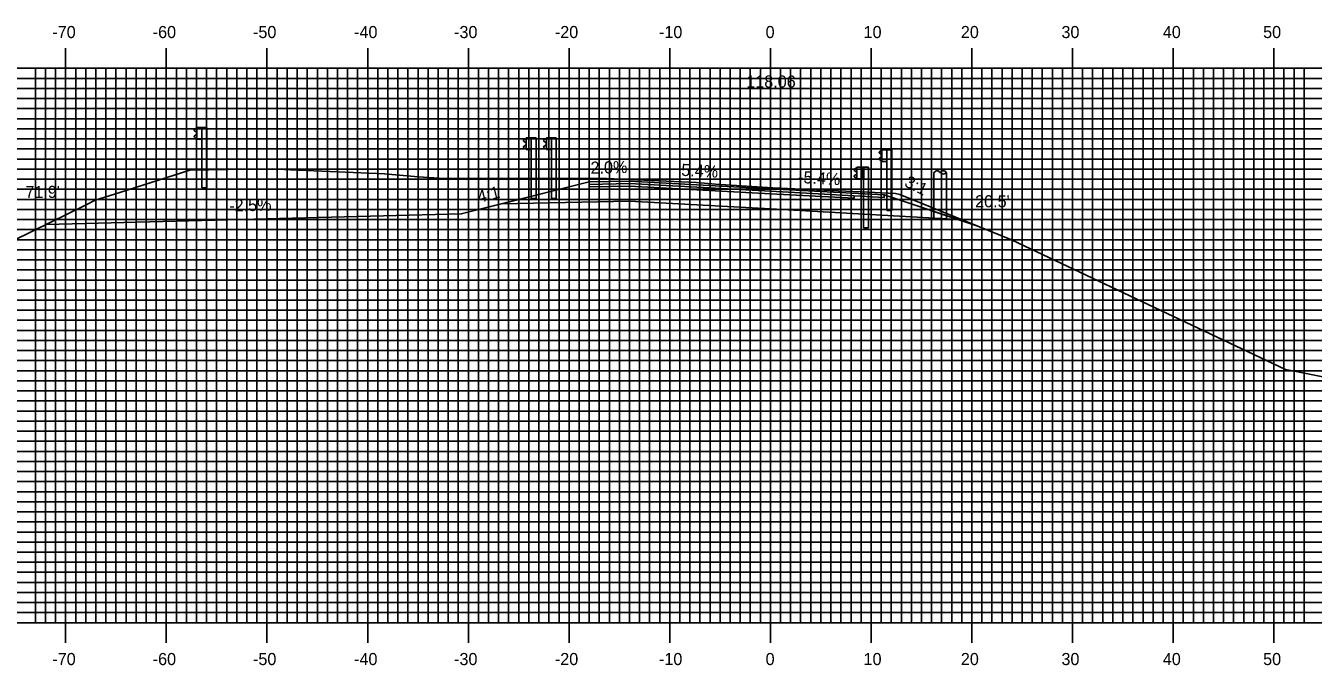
# Model space of a CAD drawing. Extents: x 1684012 to 1684355, y 461260 to 461480.
# Drawn here: x 1684103.7 to 1684231.6, y 461348.9 to 461412.3 of the extents above; entities that cross this region are included whole.
import ezdxf

# ---------------------------------------------------------------- set-up
doc = ezdxf.new("R2010")
doc.units = 0
for name, color, linetype in [('ANNOTATION', 7, 'Continuous'), ('D_Guardrail_Beam_Rt', 7, 'Continuous'), ('D_Roadway_Centerline', 7, 'Continuous'), ('D_Roadway_Centerline_Text', 7, 'Continuous'), ('D_Roadway_Edge_Shoulder', 7, 'Continuous'), ('D_Roadway_Edge_TW', 7, 'Continuous'), ('D_Roadway_Pavement', 7, 'Continuous'), ('D_Roadway_SlopeLines', 7, 'Continuous'), ('D_Roadway_SubGrade', 7, 'Continuous'), ('D_Text_Standard', 7, 'Continuous'), ('H_V ANNOTATION', 7, 'Continuous'), ('M_Guardrail', 7, 'Continuous'), ('M_Roadway_Centerline', 7, 'Continuous'), ('M_Utilities_Pole_StreetLight', 7, 'Continuous'), ('MAJOR', 7, 'Continuous'), ('MINOR', 7, 'Continuous'), ('S_Roadway_Centerline', 7, 'Continuous')]:
    doc.layers.add(name, color=color, linetype=linetype)

msp = doc.modelspace()

# ---------------------------------------------------------------- linework, layer by layer
at = {"layer": 'D_Guardrail_Beam_Rt'}
for p, q in [((1684186.17, 461398.16), (1684186.03, 461398.06)), ((1684186.03, 461397.92), (1684186.22, 461397.78)), ((1684186.22, 461397.58), (1684186.03, 461397.45)), ((1684186.03, 461397.3), (1684186.17, 461397.2)), ((1684186.26, 461398.18), (1684186.19, 461398.17)), ((1684186.19, 461397.2), (1684186.26, 461397.18)), ((1684186.26, 461398.26), (1684186.95, 461398.26)), ((1684186.26, 461397.1), (1684186.26, 461398.26)), ((1684186.26, 461397.72), (1684186.26, 461397.65)), ((1684186.78, 461398.26), (1684186.78, 461397.1)), ((1684186.89, 461398.26), (1684186.89, 461397.1)), ((1684186.95, 461398.26), (1684187.42, 461398.26)), ((1684186.95, 461398.26), (1684186.95, 461397.1)), ((1684187.42, 461398.26), (1684187.42, 461392.26)), ((1684186.95, 461397.1), (1684186.26, 461397.1)), ((1684186.93, 461392.26), (1684186.93, 461397.1)), ((1684186.93, 461392.26), (1684187.42, 461392.26))]:
    msp.add_line(p, q, dxfattribs=at)
for centre, major_axis, start_param, end_param in [((1684186.08, 461397.99), (-0.0877, 0), 5.323254, 7.243116), ((1684186.08, 461397.37), (-0.0877, 0), 5.323254, 7.243116), ((1684186.19, 461398.13), (-0.0417, 0), 4.907132, 5.323254), ((1684186.19, 461397.24), (-0.0417, 0), 0.959931, 1.376053), ((1684186.18, 461397.72), (0.0789, 0), 0, 0.959931), ((1684186.18, 461397.65), (0.0789, 0), 5.323254, 6.283185)]:
    msp.add_ellipse(centre, major_axis=major_axis, ratio=0.995501, start_param=start_param, end_param=end_param, dxfattribs=at)
at = {"layer": 'D_Roadway_Centerline'}
msp.add_lwpolyline([(1684105.77, 461392.59), (1684146.99, 461393.63), (1684150.99, 461394.63), (1684159.69, 461396.8), (1684163.69, 461396.88), (1684177.69, 461396.13), (1684187.69, 461395.59), (1684188.99, 461395.52), (1684198.19, 461392.45)], dxfattribs=at)
at = {"layer": 'D_Roadway_Edge_Shoulder'}
for points in [[(1684163.69, 461396.88), (1684159.69, 461396.8), (1684159.69, 461396.55), (1684163.69, 461396.63)], [(1684177.69, 461396.13), (1684187.69, 461395.59), (1684187.69, 461395.59), (1684188.99, 461395.52), (1684188.99, 461395.27), (1684177.69, 461395.88)], [(1684177.69, 461395.88), (1684185.99, 461395.43), (1684185.99, 461395.43), (1684185.99, 461395.43), (1684185.99, 461395.18), (1684177.69, 461395.63)]]:
    msp.add_lwpolyline(points, close=True, dxfattribs=at)
at = {"layer": 'D_Roadway_Edge_TW'}
msp.add_lwpolyline([(1684163.69, 461396.88), (1684177.69, 461396.13), (1684177.69, 461395.88), (1684163.69, 461396.63)], close=True, dxfattribs=at)
at = {"layer": 'D_Roadway_Pavement'}
for points in [[(1684163.69, 461396.63), (1684159.69, 461396.55), (1684159.69, 461396.3), (1684163.69, 461396.38)], [(1684163.69, 461396.63), (1684177.69, 461395.88), (1684177.69, 461395.63), (1684163.69, 461396.38)]]:
    msp.add_lwpolyline(points, close=True, dxfattribs=at)
msp.add_lwpolyline([(1684177.69, 461395.88), (1684177.69, 461395.63)], dxfattribs=at)
msp.add_lwpolyline([(1684177.69, 461395.88), (1684177.69, 461395.63)], dxfattribs=at)
msp.add_lwpolyline([(1684177.69, 461395.88), (1684177.69, 461395.63)], dxfattribs=at)
at = {"layer": 'D_Roadway_SlopeLines'}
for points in [[(1684159.69, 461396.8), (1684146.99, 461393.63)], [(1684146.99, 461393.63), (1684105.77, 461392.59)]]:
    msp.add_lwpolyline(points, dxfattribs=at)
at = {"layer": 'D_Roadway_SubGrade'}
for points in [[(1684163.69, 461396.38), (1684159.69, 461396.3), (1684159.69, 461396.55), (1684159.69, 461396.8), (1684150.99, 461394.63), (1684163.69, 461394.88)], [(1684163.69, 461396.38), (1684177.69, 461395.63), (1684177.69, 461394.13), (1684163.69, 461394.88)], [(1684177.69, 461395.63), (1684177.69, 461395.88), (1684188.99, 461395.27), (1684188.99, 461395.52), (1684196.33, 461393.07), (1684177.69, 461394.13)]]:
    msp.add_lwpolyline(points, close=True, dxfattribs=at)
at = {"layer": 'M_Guardrail'}
for p, q in [((1684120.63, 461402.1), (1684120.49, 461402)), ((1684120.49, 461401.86), (1684120.68, 461401.72)), ((1684120.68, 461401.5), (1684120.49, 461401.37)), ((1684120.49, 461401.22), (1684120.63, 461401.12)), ((1684120.73, 461402.12), (1684120.65, 461402.11)), ((1684120.65, 461401.12), (1684120.73, 461401.1)), ((1684120.72, 461401.66), (1684120.72, 461401.57)), ((1684120.73, 461402.2), (1684121.22, 461402.2)), ((1684120.73, 461401.03), (1684120.73, 461402.2)), ((1684121.22, 461401.03), (1684120.73, 461401.03)), ((1684121.22, 461402.2), (1684121.71, 461402.2)), ((1684121.22, 461402.2), (1684121.22, 461401.03)), ((1684121.22, 461396.2), (1684121.22, 461401.03)), ((1684121.71, 461402.2), (1684121.71, 461396.2)), ((1684153.34, 461401.07), (1684153.2, 461400.97)), ((1684153.44, 461401.09), (1684153.36, 461401.08)), ((1684153.44, 461401.16), (1684153.93, 461401.16)), ((1684153.44, 461400), (1684153.44, 461401.16)), ((1684153.93, 461401.16), (1684154.42, 461401.16)), ((1684153.93, 461401.16), (1684153.93, 461400)), ((1684154.42, 461401.16), (1684154.42, 461395.16)), ((1684155.34, 461401.07), (1684155.2, 461400.97)), ((1684155.44, 461401.09), (1684155.36, 461401.08)), ((1684155.44, 461401.16), (1684155.93, 461401.16)), ((1684155.44, 461400), (1684155.44, 461401.16)), ((1684155.93, 461401.16), (1684156.42, 461401.16)), ((1684155.93, 461401.16), (1684155.93, 461400)), ((1684156.42, 461401.16), (1684156.42, 461395.16)), ((1684153.2, 461400.83), (1684153.4, 461400.69)), ((1684153.4, 461400.47), (1684153.2, 461400.33)), ((1684153.2, 461400.19), (1684153.34, 461400.09)), ((1684153.36, 461400.08), (1684153.44, 461400.07)), ((1684153.43, 461400.62), (1684153.43, 461400.53)), ((1684153.93, 461400), (1684153.44, 461400)), ((1684153.93, 461395.16), (1684153.93, 461400)), ((1684155.2, 461400.83), (1684155.4, 461400.69)), ((1684155.4, 461400.47), (1684155.2, 461400.33)), ((1684155.2, 461400.19), (1684155.34, 461400.09)), ((1684155.36, 461400.08), (1684155.44, 461400.07)), ((1684155.43, 461400.62), (1684155.43, 461400.53)), ((1684155.93, 461400), (1684155.44, 461400)), ((1684155.93, 461395.16), (1684155.93, 461400)), ((1684188.66, 461399.89), (1684188.52, 461399.79)), ((1684188.76, 461399.91), (1684188.68, 461399.9)), ((1684188.76, 461399.98), (1684189.25, 461399.98)), ((1684188.76, 461398.82), (1684188.76, 461399.98)), ((1684189.25, 461399.98), (1684189.74, 461399.98)), ((1684189.25, 461399.98), (1684189.25, 461398.82)), ((1684189.74, 461399.98), (1684189.74, 461393.98)), ((1684188.52, 461399.65), (1684188.72, 461399.51)), ((1684188.72, 461399.29), (1684188.52, 461399.15)), ((1684188.52, 461399.01), (1684188.66, 461398.91)), ((1684188.68, 461398.9), (1684188.76, 461398.89)), ((1684188.75, 461399.45), (1684188.75, 461399.35)), ((1684189.25, 461398.82), (1684188.76, 461398.82)), ((1684189.25, 461393.98), (1684189.25, 461398.82)), ((1684121.22, 461396.2), (1684121.71, 461396.2)), ((1684153.93, 461395.16), (1684154.42, 461395.16)), ((1684155.93, 461395.16), (1684156.42, 461395.16)), ((1684189.25, 461393.98), (1684189.74, 461393.98))]:
    msp.add_line(p, q, dxfattribs=at)
for centre, major_axis, start_param, end_param in [((1684120.54, 461401.93), (-0.0877, 0), 5.323254, 7.243116), ((1684120.54, 461401.3), (-0.0877, 0), 5.323254, 7.243116), ((1684120.65, 461402.07), (-0.0417, 0), 4.886922, 5.323254), ((1684120.65, 461401.16), (-0.0417, 0), 0.959931, 1.396263), ((1684120.64, 461401.66), (0.0789, 0), 0, 0.959931), ((1684120.64, 461401.57), (0.0789, 0), 5.323254, 6.283185), ((1684153.37, 461401.03), (-0.0417, 0), 4.886922, 5.323254), ((1684155.37, 461401.03), (-0.0417, 0), 4.886922, 5.323254), ((1684153.25, 461400.9), (-0.0877, 0), 5.323254, 7.243116), ((1684153.25, 461400.26), (-0.0877, 0), 5.323254, 7.243116), ((1684153.37, 461400.12), (-0.0417, 0), 0.959931, 1.396263), ((1684153.35, 461400.62), (0.0789, 0), 0, 0.959931), ((1684153.35, 461400.53), (0.0789, 0), 5.323254, 6.283185), ((1684155.25, 461400.9), (-0.0877, 0), 5.323254, 7.243116), ((1684155.25, 461400.26), (-0.0877, 0), 5.323254, 7.243116), ((1684155.37, 461400.12), (-0.0417, 0), 0.959931, 1.396263), ((1684155.35, 461400.62), (0.0789, 0), 0, 0.959931), ((1684155.35, 461400.53), (0.0789, 0), 5.323254, 6.283185), ((1684188.57, 461399.72), (-0.0877, 0), 5.323254, 7.243116), ((1684188.69, 461399.86), (-0.0417, 0), 4.886922, 5.323254), ((1684188.57, 461399.08), (-0.0877, 0), 5.323254, 7.243116), ((1684188.69, 461398.95), (-0.0417, 0), 0.959931, 1.396263), ((1684188.67, 461399.45), (0.0789, 0), 0, 0.959931), ((1684188.67, 461399.35), (0.0789, 0), 5.323254, 6.283185)]:
    msp.add_ellipse(centre, major_axis=major_axis, ratio=0.995501, start_param=start_param, end_param=end_param, dxfattribs=at)
at = {"layer": 'M_Utilities_Pole_StreetLight'}
for p, q in [((1684193.93, 461397.74), (1684194.09, 461397.85)), ((1684193.93, 461393.12), (1684193.93, 461397.74)), ((1684194.4, 461397.85), (1684194.56, 461397.74)), ((1684194.72, 461397.85), (1684194.56, 461397.74)), ((1684194.56, 461397.74), (1684194.72, 461397.63)), ((1684195.18, 461397.74), (1684195.03, 461397.85)), ((1684195.03, 461397.63), (1684195.18, 461397.74)), ((1684195.18, 461393.12), (1684195.18, 461397.74))]:
    msp.add_line(p, q, dxfattribs=at)
for centre, start, end in [((1684194.25, 461397.63), 90, 125.2644), ((1684194.25, 461397.63), 54.7356, 90), ((1684194.87, 461397.63), 90, 125.2644), ((1684194.87, 461397.85), 234.7356, 270), ((1684194.87, 461397.63), 54.7356, 90), ((1684194.87, 461397.85), 270, 305.2644)]:
    msp.add_arc(centre, 0.271, start, end, dxfattribs=at)
at = {"layer": 'MAJOR'}
for p, q in [((1684107.69, 461410.08), (1684107.69, 461408.07)), ((1684117.69, 461410.08), (1684117.69, 461408.07)), ((1684127.69, 461410.08), (1684127.69, 461408.07)), ((1684137.69, 461410.08), (1684137.69, 461408.07)), ((1684147.69, 461410.08), (1684147.69, 461408.07)), ((1684157.69, 461410.08), (1684157.69, 461408.07)), ((1684167.69, 461410.08), (1684167.69, 461408.07)), ((1684177.69, 461410.08), (1684177.69, 461408.07)), ((1684187.69, 461410.08), (1684187.69, 461408.07)), ((1684197.69, 461410.08), (1684197.69, 461408.07)), ((1684207.69, 461410.08), (1684207.69, 461408.07)), ((1684217.69, 461410.08), (1684217.69, 461408.07)), ((1684227.69, 461410.08), (1684227.69, 461408.07)), ((1684037.69, 461408.07), (1684317.69, 461408.07)), ((1684037.69, 461408.07), (1684317.69, 461408.07)), ((1684107.69, 461353.07), (1684107.69, 461408.07)), ((1684117.69, 461353.07), (1684117.69, 461408.07)), ((1684127.69, 461353.07), (1684127.69, 461408.07)), ((1684137.69, 461353.07), (1684137.69, 461408.07)), ((1684147.69, 461353.07), (1684147.69, 461408.07)), ((1684157.69, 461353.07), (1684157.69, 461408.07)), ((1684167.69, 461353.07), (1684167.69, 461408.07)), ((1684177.69, 461353.07), (1684177.69, 461408.07)), ((1684187.69, 461353.07), (1684187.69, 461408.07)), ((1684197.69, 461353.07), (1684197.69, 461408.07)), ((1684207.69, 461353.07), (1684207.69, 461408.07)), ((1684217.69, 461353.07), (1684217.69, 461408.07)), ((1684227.69, 461353.07), (1684227.69, 461408.07)), ((1684037.69, 461403.07), (1684317.69, 461403.07)), ((1684037.69, 461398.07), (1684317.69, 461398.07)), ((1684037.69, 461393.07), (1684317.69, 461393.07)), ((1684037.69, 461388.07), (1684317.69, 461388.07)), ((1684037.69, 461383.07), (1684317.69, 461383.07)), ((1684037.69, 461378.07), (1684317.69, 461378.07)), ((1684037.69, 461373.07), (1684317.69, 461373.07)), ((1684037.69, 461368.07), (1684317.69, 461368.07)), ((1684037.69, 461363.07), (1684317.69, 461363.07)), ((1684037.69, 461358.07), (1684317.69, 461358.07)), ((1684037.69, 461353.07), (1684317.69, 461353.07)), ((1684037.69, 461353.07), (1684317.69, 461353.07)), ((1684107.69, 461351.07), (1684107.69, 461353.07)), ((1684117.69, 461351.07), (1684117.69, 461353.07)), ((1684127.69, 461351.07), (1684127.69, 461353.07)), ((1684137.69, 461351.07), (1684137.69, 461353.07)), ((1684147.69, 461351.07), (1684147.69, 461353.07)), ((1684157.69, 461351.07), (1684157.69, 461353.07)), ((1684167.69, 461351.07), (1684167.69, 461353.07)), ((1684177.69, 461351.07), (1684177.69, 461353.07)), ((1684187.69, 461351.07), (1684187.69, 461353.07)), ((1684197.69, 461351.07), (1684197.69, 461353.07)), ((1684207.69, 461351.07), (1684207.69, 461353.07)), ((1684217.69, 461351.07), (1684217.69, 461353.07)), ((1684227.69, 461351.07), (1684227.69, 461353.07))]:
    msp.add_line(p, q, dxfattribs=at)
at = {"layer": 'MINOR'}
for p, q in [((1684104.69, 461353.07), (1684104.69, 461408.07)), ((1684105.69, 461353.07), (1684105.69, 461408.07)), ((1684106.69, 461353.07), (1684106.69, 461408.07)), ((1684108.69, 461353.07), (1684108.69, 461408.07)), ((1684109.69, 461353.07), (1684109.69, 461408.07)), ((1684110.69, 461353.07), (1684110.69, 461408.07)), ((1684111.69, 461353.07), (1684111.69, 461408.07)), ((1684112.69, 461353.07), (1684112.69, 461408.07)), ((1684113.69, 461353.07), (1684113.69, 461408.07)), ((1684114.69, 461353.07), (1684114.69, 461408.07)), ((1684115.69, 461353.07), (1684115.69, 461408.07)), ((1684116.69, 461353.07), (1684116.69, 461408.07)), ((1684118.69, 461353.07), (1684118.69, 461408.07)), ((1684119.69, 461353.07), (1684119.69, 461408.07)), ((1684120.69, 461353.07), (1684120.69, 461408.07)), ((1684121.69, 461353.07), (1684121.69, 461408.07)), ((1684122.69, 461353.07), (1684122.69, 461408.07)), ((1684123.69, 461353.07), (1684123.69, 461408.07)), ((1684124.69, 461353.07), (1684124.69, 461408.07)), ((1684125.69, 461353.07), (1684125.69, 461408.07)), ((1684126.69, 461353.07), (1684126.69, 461408.07)), ((1684128.69, 461353.07), (1684128.69, 461408.07)), ((1684129.69, 461353.07), (1684129.69, 461408.07)), ((1684130.69, 461353.07), (1684130.69, 461408.07)), ((1684131.69, 461353.07), (1684131.69, 461408.07)), ((1684132.69, 461353.07), (1684132.69, 461408.07)), ((1684133.69, 461353.07), (1684133.69, 461408.07)), ((1684134.69, 461353.07), (1684134.69, 461408.07)), ((1684135.69, 461353.07), (1684135.69, 461408.07)), ((1684136.69, 461353.07), (1684136.69, 461408.07)), ((1684138.69, 461353.07), (1684138.69, 461408.07)), ((1684139.69, 461353.07), (1684139.69, 461408.07)), ((1684140.69, 461353.07), (1684140.69, 461408.07)), ((1684141.69, 461353.07), (1684141.69, 461408.07)), ((1684142.69, 461353.07), (1684142.69, 461408.07)), ((1684143.69, 461353.07), (1684143.69, 461408.07)), ((1684144.69, 461353.07), (1684144.69, 461408.07)), ((1684145.69, 461353.07), (1684145.69, 461408.07)), ((1684146.69, 461353.07), (1684146.69, 461408.07)), ((1684148.69, 461353.07), (1684148.69, 461408.07)), ((1684149.69, 461353.07), (1684149.69, 461408.07)), ((1684150.69, 461353.07), (1684150.69, 461408.07)), ((1684151.69, 461353.07), (1684151.69, 461408.07)), ((1684152.69, 461353.07), (1684152.69, 461408.07)), ((1684153.69, 461353.07), (1684153.69, 461408.07)), ((1684154.69, 461353.07), (1684154.69, 461408.07)), ((1684155.69, 461353.07), (1684155.69, 461408.07)), ((1684156.69, 461353.07), (1684156.69, 461408.07)), ((1684158.69, 461353.07), (1684158.69, 461408.07)), ((1684159.69, 461353.07), (1684159.69, 461408.07)), ((1684160.69, 461353.07), (1684160.69, 461408.07)), ((1684161.69, 461353.07), (1684161.69, 461408.07)), ((1684162.69, 461353.07), (1684162.69, 461408.07)), ((1684163.69, 461353.07), (1684163.69, 461408.07)), ((1684164.69, 461353.07), (1684164.69, 461408.07)), ((1684165.69, 461353.07), (1684165.69, 461408.07)), ((1684166.69, 461353.07), (1684166.69, 461408.07)), ((1684168.69, 461353.07), (1684168.69, 461408.07)), ((1684169.69, 461353.07), (1684169.69, 461408.07)), ((1684170.69, 461353.07), (1684170.69, 461408.07)), ((1684171.69, 461353.07), (1684171.69, 461408.07)), ((1684172.69, 461353.07), (1684172.69, 461408.07)), ((1684173.69, 461353.07), (1684173.69, 461408.07)), ((1684174.69, 461353.07), (1684174.69, 461408.07)), ((1684175.69, 461353.07), (1684175.69, 461408.07)), ((1684176.69, 461353.07), (1684176.69, 461408.07)), ((1684178.69, 461353.07), (1684178.69, 461408.07)), ((1684179.69, 461353.07), (1684179.69, 461408.07)), ((1684180.69, 461353.07), (1684180.69, 461408.07)), ((1684181.69, 461353.07), (1684181.69, 461408.07)), ((1684182.69, 461353.07), (1684182.69, 461408.07)), ((1684183.69, 461353.07), (1684183.69, 461408.07)), ((1684184.69, 461353.07), (1684184.69, 461408.07)), ((1684185.69, 461353.07), (1684185.69, 461408.07)), ((1684186.69, 461353.07), (1684186.69, 461408.07)), ((1684188.69, 461353.07), (1684188.69, 461408.07)), ((1684189.69, 461353.07), (1684189.69, 461408.07)), ((1684190.69, 461353.07), (1684190.69, 461408.07)), ((1684191.69, 461353.07), (1684191.69, 461408.07)), ((1684192.69, 461353.07), (1684192.69, 461408.07)), ((1684193.69, 461353.07), (1684193.69, 461408.07)), ((1684194.69, 461353.07), (1684194.69, 461408.07)), ((1684195.69, 461353.07), (1684195.69, 461408.07)), ((1684196.69, 461353.07), (1684196.69, 461408.07)), ((1684198.69, 461353.07), (1684198.69, 461408.07)), ((1684199.69, 461353.07), (1684199.69, 461408.07)), ((1684200.69, 461353.07), (1684200.69, 461408.07)), ((1684201.69, 461353.07), (1684201.69, 461408.07)), ((1684202.69, 461353.07), (1684202.69, 461408.07)), ((1684203.69, 461353.07), (1684203.69, 461408.07)), ((1684204.69, 461353.07), (1684204.69, 461408.07)), ((1684205.69, 461353.07), (1684205.69, 461408.07)), ((1684206.69, 461353.07), (1684206.69, 461408.07)), ((1684208.69, 461353.07), (1684208.69, 461408.07)), ((1684209.69, 461353.07), (1684209.69, 461408.07)), ((1684210.69, 461353.07), (1684210.69, 461408.07)), ((1684211.69, 461353.07), (1684211.69, 461408.07)), ((1684212.69, 461353.07), (1684212.69, 461408.07)), ((1684213.69, 461353.07), (1684213.69, 461408.07)), ((1684214.69, 461353.07), (1684214.69, 461408.07)), ((1684215.69, 461353.07), (1684215.69, 461408.07)), ((1684216.69, 461353.07), (1684216.69, 461408.07)), ((1684218.69, 461353.07), (1684218.69, 461408.07)), ((1684219.69, 461353.07), (1684219.69, 461408.07)), ((1684220.69, 461353.07), (1684220.69, 461408.07)), ((1684221.69, 461353.07), (1684221.69, 461408.07)), ((1684222.69, 461353.07), (1684222.69, 461408.07)), ((1684223.69, 461353.07), (1684223.69, 461408.07)), ((1684224.69, 461353.07), (1684224.69, 461408.07)), ((1684225.69, 461353.07), (1684225.69, 461408.07)), ((1684226.69, 461353.07), (1684226.69, 461408.07)), ((1684228.69, 461353.07), (1684228.69, 461408.07)), ((1684229.69, 461353.07), (1684229.69, 461408.07)), ((1684230.69, 461353.07), (1684230.69, 461408.07)), ((1684037.69, 461407.07), (1684317.69, 461407.07)), ((1684037.69, 461406.07), (1684317.69, 461406.07)), ((1684037.69, 461405.07), (1684317.69, 461405.07)), ((1684037.69, 461404.07), (1684317.69, 461404.07)), ((1684037.69, 461402.07), (1684317.69, 461402.07)), ((1684037.69, 461401.07), (1684317.69, 461401.07)), ((1684037.69, 461400.07), (1684317.69, 461400.07)), ((1684037.69, 461399.07), (1684317.69, 461399.07)), ((1684037.69, 461397.07), (1684317.69, 461397.07)), ((1684037.69, 461396.07), (1684317.69, 461396.07)), ((1684037.69, 461395.07), (1684317.69, 461395.07)), ((1684037.69, 461394.07), (1684317.69, 461394.07)), ((1684037.69, 461392.07), (1684317.69, 461392.07)), ((1684037.69, 461391.07), (1684317.69, 461391.07)), ((1684037.69, 461390.07), (1684317.69, 461390.07)), ((1684037.69, 461389.07), (1684317.69, 461389.07)), ((1684037.69, 461387.07), (1684317.69, 461387.07)), ((1684037.69, 461386.07), (1684317.69, 461386.07)), ((1684037.69, 461385.07), (1684317.69, 461385.07)), ((1684037.69, 461384.07), (1684317.69, 461384.07)), ((1684037.69, 461382.07), (1684317.69, 461382.07)), ((1684037.69, 461381.07), (1684317.69, 461381.07)), ((1684037.69, 461380.07), (1684317.69, 461380.07)), ((1684037.69, 461379.07), (1684317.69, 461379.07)), ((1684037.69, 461377.07), (1684317.69, 461377.07)), ((1684037.69, 461376.07), (1684317.69, 461376.07)), ((1684037.69, 461375.07), (1684317.69, 461375.07)), ((1684037.69, 461374.07), (1684317.69, 461374.07)), ((1684037.69, 461372.07), (1684317.69, 461372.07)), ((1684037.69, 461371.07), (1684317.69, 461371.07)), ((1684037.69, 461370.07), (1684317.69, 461370.07)), ((1684037.69, 461369.07), (1684317.69, 461369.07)), ((1684037.69, 461367.07), (1684317.69, 461367.07)), ((1684037.69, 461366.07), (1684317.69, 461366.07)), ((1684037.69, 461365.07), (1684317.69, 461365.07)), ((1684037.69, 461364.07), (1684317.69, 461364.07)), ((1684037.69, 461362.07), (1684317.69, 461362.07)), ((1684037.69, 461361.07), (1684317.69, 461361.07)), ((1684037.69, 461360.07), (1684317.69, 461360.07)), ((1684037.69, 461359.07), (1684317.69, 461359.07)), ((1684037.69, 461357.07), (1684317.69, 461357.07)), ((1684037.69, 461356.07), (1684317.69, 461356.07)), ((1684037.69, 461355.07), (1684317.69, 461355.07)), ((1684037.69, 461354.07), (1684317.69, 461354.07))]:
    msp.add_line(p, q, dxfattribs=at)
at = {"layer": 'S_Roadway_Centerline'}
msp.add_lwpolyline([(1684102.5, 461391), (1684109.72, 461394.52), (1684110.63, 461394.99), (1684113.09, 461395.75), (1684120.03, 461397.97), (1684123.83, 461398.03), (1684128.25, 461398.09), (1684130.01, 461398.01), (1684139.37, 461397.59), (1684142.71, 461397.32), (1684144.79, 461397.18), (1684155.04, 461397.13), (1684161.45, 461397.13), (1684166.59, 461396.9), (1684170.33, 461396.73), (1684172.24, 461396.58), (1684177.94, 461396.2), (1684188.05, 461395.74), (1684190.11, 461395.64), (1684190.54, 461395.56), (1684201.62, 461391.06), (1684226.34, 461379.39), (1684228.84, 461378.18), (1684229.58, 461378.06), (1684236.38, 461376.72)], dxfattribs=at)

# ---------------------------------------------------------------- texts
at = {"layer": 'ANNOTATION'}
for s, rotation, p in [('-2.0%', 1.1458, (1684159.3, 461397.6)), ('5.4%', 356.909, (1684168.81, 461397.41)), ('-5.4%', 356.909, (1684180.41, 461396.7)), ('3:1', 333.4349, (1684190.91, 461396.41)), ('4:1', 14.0362, (1684148.75, 461394.71)), ('-2.5%', 1.4415, (1684123.96, 461393.85))]:
    msp.add_text(s, height=1.2, rotation=rotation, dxfattribs=at).set_placement(p)
at = {"layer": 'D_Roadway_Centerline_Text'}
msp.add_text('118.06', height=1.2, dxfattribs=at).set_placement((1684175.29, 461406.16))
at = {"layer": 'D_Text_Standard'}
for s, p in [("71.9'", (1684103.69, 461395.21)), ("20.5'", (1684198.02, 461394.28))]:
    msp.add_text(s, height=1.2, dxfattribs=at).set_placement(p)
at = {"layer": 'H_V ANNOTATION'}
for s, p in [('-70', (1684106.37, 461411.07)), ('-60', (1684116.34, 461411.07)), ('-50', (1684126.3, 461411.07)), ('-40', (1684136.34, 461411.07)), ('-30', (1684146.27, 461411.07)), ('-20', (1684156.28, 461411.07)), ('-10', (1684166.62, 461411.07)), ('0', (1684177.21, 461411.07)), ('10', (1684186.94, 461411.07)), ('20', (1684196.6, 461411.07)), ('30', (1684206.59, 461411.07)), ('40', (1684216.66, 461411.07)), ('50', (1684226.62, 461411.07)), ('-70', (1684106.37, 461348.87)), ('-60', (1684116.34, 461348.87)), ('-50', (1684126.3, 461348.87)), ('-40', (1684136.34, 461348.87)), ('-30', (1684146.27, 461348.87)), ('-20', (1684156.28, 461348.87)), ('-10', (1684166.62, 461348.87)), ('0', (1684177.21, 461348.87)), ('10', (1684186.94, 461348.87)), ('20', (1684196.6, 461348.87)), ('30', (1684206.59, 461348.87)), ('40', (1684216.66, 461348.87)), ('50', (1684226.62, 461348.87))]:
    msp.add_text(s, height=1.2, dxfattribs=at).set_placement(p)
at = {"layer": 'M_Roadway_Centerline'}
for s, p in [('C', (1684139.36, 461397.59)), ('L', (1684139.37, 461397.58)), ('C', (1684170.33, 461396.73)), ('L', (1684170.33, 461396.72))]:
    msp.add_text(s, height=0.0146, dxfattribs=at).set_placement(p)

doc.saveas('drawing.dxf')
